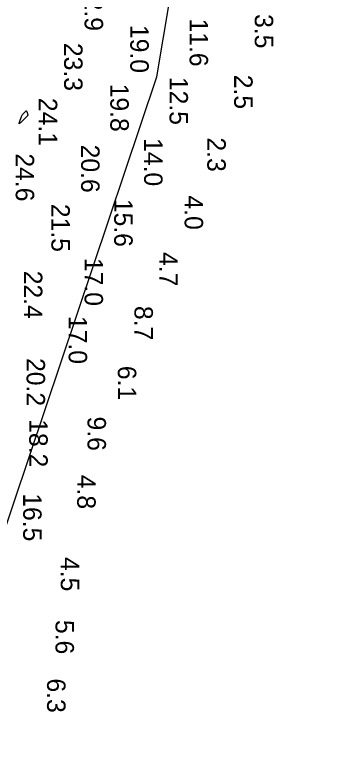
# Model space of a CAD drawing. Extents: x 1178573 to 1187098, y 693282 to 751751.
# Drawn here: x 1186743.6 to 1186962.9, y 728159.6 to 728655.4 of the extents above; entities that cross this region are included whole.
import ezdxf

# ---------------------------------------------------------------- set-up
doc = ezdxf.new("R2010")
doc.units = 0
for name, color, linetype in [('G-ANNO-PATT', 7, 'Continuous'), ('V-HYDS-MAJR', 7, 'Continuous'), ('V-HYDS-SOUN', 7, 'Continuous')]:
    doc.layers.add(name, color=color, linetype=linetype)

msp = doc.modelspace()

# ---------------------------------------------------------------- linework, layer by layer
at = {"layer": 'G-ANNO-PATT'}
for p, q in [((1186839.88, 728613.33), (1186962.87, 729346.34)), ((1186337.91, 727120.31), (1186839.88, 728613.33)), ((1186752.27, 728586.92), (1186747.47, 728582.1)), ((1186748.22, 728586.41), (1186748.43, 728586.91)), ((1186748.43, 728586.91), (1186748.69, 728587.38)), ((1186748.69, 728587.38), (1186749, 728587.83)), ((1186749, 728587.83), (1186749.35, 728588.24)), ((1186749.35, 728588.24), (1186751.1, 728590.06)), ((1186751.1, 728590.06), (1186751.34, 728590.26)), ((1186751.34, 728590.26), (1186751.55, 728590.29)), ((1186751.55, 728590.29), (1186751.71, 728590.16)), ((1186751.71, 728590.16), (1186751.83, 728589.87)), ((1186751.83, 728589.87), (1186752.41, 728587.68)), ((1186752.29, 728586.95), (1186752.27, 728586.92)), ((1186752.31, 728586.98), (1186752.29, 728586.95)), ((1186752.33, 728587.02), (1186752.31, 728586.98)), ((1186752.34, 728587.06), (1186752.33, 728587.02)), ((1186752.37, 728587.22), (1186752.34, 728587.06)), ((1186752.38, 728587.26), (1186752.37, 728587.22)), ((1186752.39, 728587.3), (1186752.38, 728587.26)), ((1186752.4, 728587.38), (1186752.39, 728587.34)), ((1186752.39, 728587.34), (1186752.39, 728587.3)), ((1186752.42, 728587.53), (1186752.4, 728587.38)), ((1186752.41, 728587.68), (1186752.42, 728587.64)), ((1186752.42, 728587.64), (1186752.42, 728587.61)), ((1186752.42, 728587.61), (1186752.42, 728587.57)), ((1186752.42, 728587.57), (1186752.42, 728587.53)), ((1186746.64, 728581.86), (1186746.82, 728582.51)), ((1186746.69, 728581.58), (1186746.64, 728581.86)), ((1186746.82, 728582.51), (1186748.22, 728586.41)), ((1186747.47, 728582.1), (1186746.96, 728581.66)), ((1186746.96, 728581.66), (1186746.69, 728581.58))]:
    msp.add_line(p, q, dxfattribs=at)
at = {"layer": 'V-HYDS-MAJR'}
msp.add_lwpolyline([(1186748.69, 728587.38), (1186749, 728587.83), (1186749.35, 728588.24), (1186751.1, 728590.06), (1186751.34, 728590.26), (1186751.55, 728590.29), (1186751.71, 728590.16), (1186751.83, 728589.87), (1186752.41, 728587.68), (1186752.42, 728587.64), (1186752.42, 728587.61), (1186752.42, 728587.57), (1186752.42, 728587.53), (1186752.4, 728587.38), (1186752.39, 728587.34), (1186752.39, 728587.3), (1186752.38, 728587.26), (1186752.37, 728587.22), (1186752.34, 728587.06), (1186752.33, 728587.02), (1186752.31, 728586.98), (1186752.29, 728586.95), (1186752.27, 728586.92), (1186747.47, 728582.1), (1186746.96, 728581.66), (1186746.69, 728581.58), (1186746.64, 728581.86), (1186746.82, 728582.51), (1186748.22, 728586.41), (1186748.43, 728586.91)], close=True, dxfattribs=at)

# ---------------------------------------------------------------- texts
at = {"layer": 'V-HYDS-SOUN'}
for s, p in [('22.9 ', (1186790.97, 728676.83)), ('11.6 ', (1186862.09, 728652.75)), ('3.5', (1186906.23, 728655.73)), ('19.0 ', (1186821.9, 728648.4)), ('23.3 ', (1186777.08, 728636.25)), ('12.5 ', (1186848.48, 728613.26)), ('2.5', (1186892.28, 728614.69)), ('19.8 ', (1186808.39, 728608.66)), ('24.1 ', (1186759.94, 728599.04)), ('14.0 ', (1186831.28, 728571.82)), ('2.3', (1186874.07, 728572.28)), ('20.6 ', (1186788.6, 728567.39)), ('24.6 ', (1186744.28, 728561.48)), ('4.0', (1186858.72, 728533.01)), ('15.6 ', (1186811.01, 728530.74)), ('21.5 ', (1186768.46, 728527.34)), ('4.7', (1186841.53, 728494.75)), ('17.0 ', (1186790.93, 728490.76)), ('22.4 ', (1186749.82, 728482.09)), ('8.7', (1186824.73, 728458.27)), ('17.0 ', (1186780.17, 728451.48)), ('20.2 ', (1186751.65, 728422.99)), ('6.1', (1186813.48, 728417.72)), ('18.2 ', (1186753.45, 728381.62)), ('9.6', (1186792.94, 728383.4)), ('4.8', (1186785.95, 728344.01)), ('16.5 ', (1186749.34, 728331.47)), ('4.5', (1186774.83, 728288.34)), ('5.6', (1186771.25, 728245.77)), ('6.3', (1186765.54, 728206.17))]:
    msp.add_text(s, height=12.5, rotation=270, dxfattribs=at).set_placement(p)

doc.saveas('drawing.dxf')
